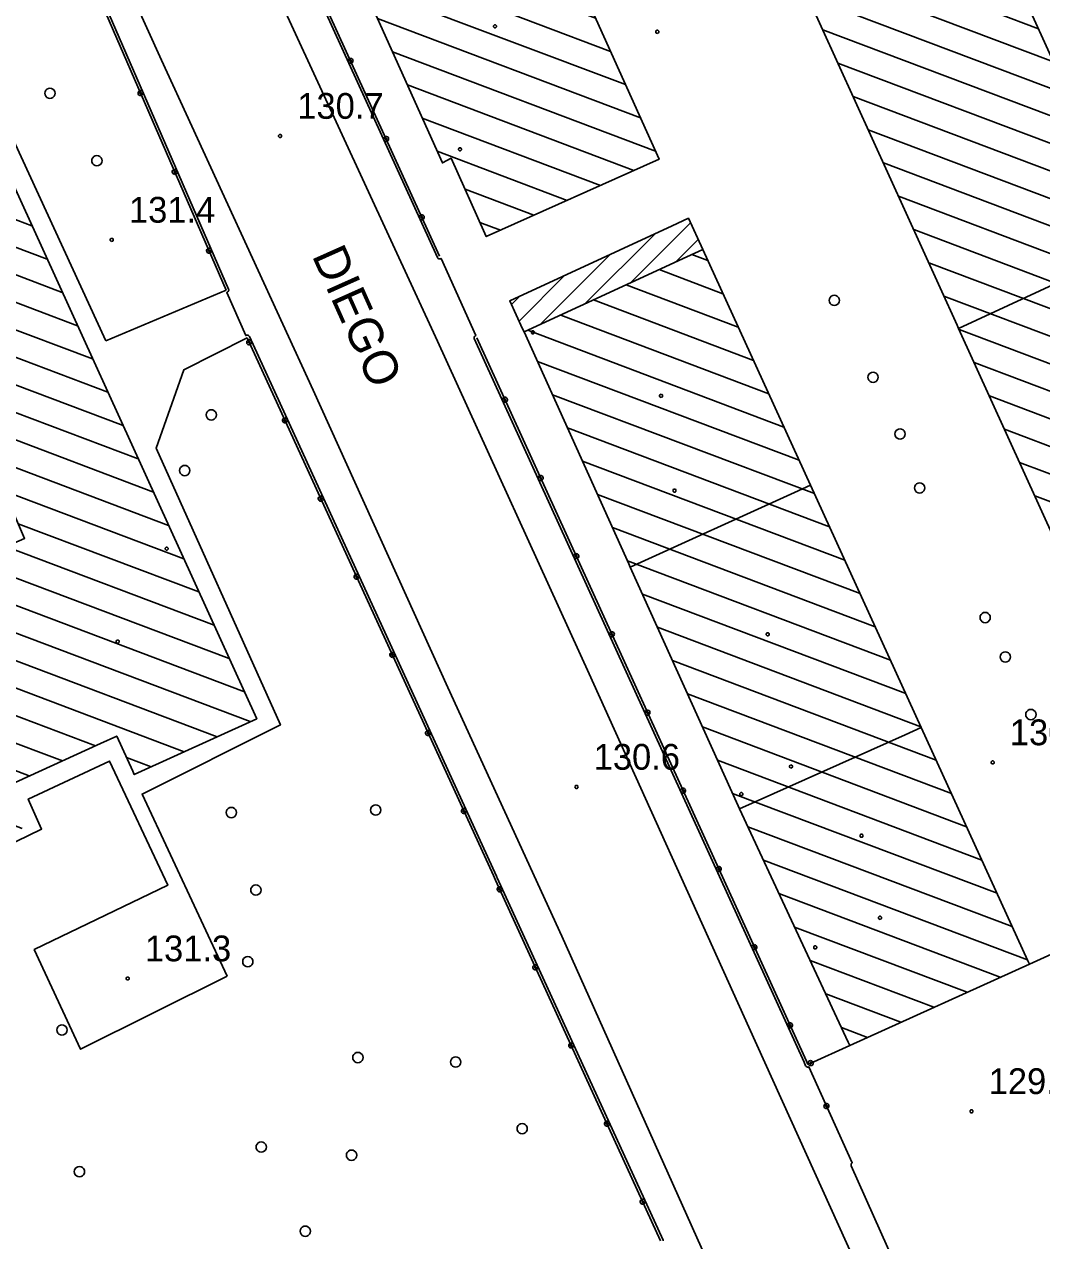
# Model space of a CAD drawing. Extents: x 513373 to 514978, y 5038576 to 5040180.
# Drawn here: x 513491.5 to 513550.7, y 5038719.9 to 5038790.7 of the extents above; entities that cross this region are included whole.
import ezdxf

# ---------------------------------------------------------------- set-up
doc = ezdxf.new("R2010")
doc.units = 0
for name, color, linetype in [('2010300', 7, 'Continuous'), ('3010204', 7, 'Continuous'), ('B1211', 7, 'Continuous'), ('C1131', 7, 'Continuous'), ('C12211', 7, 'Continuous'), ('C21111', 7, 'Continuous'), ('C2911', 7, 'Continuous'), ('C2912', 7, 'Continuous'), ('CAMP_C12211', 7, 'Continuous'), ('CAMP_C21111', 7, 'Continuous'), ('Default', 7, 'Continuous'), ('F12107', 7, 'Continuous'), ('F12131', 7, 'Continuous'), ('F12132', 7, 'Continuous'), ('G4315', 7, 'Continuous'), ('TOP500', 7, 'Continuous'), ('TOP920', 7, 'Continuous')]:
    doc.layers.add(name, color=color, linetype=linetype)

# ---------------------------------------------------------------- blocks, each defined once
blk = doc.blocks.new('CAMP_7F96C5B8')
at = {"layer": 'CAMP_C12211'}
for p, q in [((-4.396, 23.309), (-5.045, 23.554)), ((-3.525, 21.376), (-6.942, 22.667)), ((-2.655, 19.444), (-8.838, 21.78)), ((-1.784, 17.511), (-10.734, 20.893)), ((-0.913, 15.578), (-12.63, 20.006)), ((-0.042, 13.646), (-14.476, 19.1)), ((0.829, 11.713), (-13.611, 17.169)), ((1.7, 9.78), (-12.746, 15.239)), ((2.571, 7.848), (-12.64, 13.595)), ((3.442, 5.915), (-11.774, 11.665)), ((4.313, 3.983), (-10.909, 9.735)), ((5.184, 2.05), (-10.044, 7.804)), ((6.055, 0.117), (-9.179, 5.874)), ((6.926, -1.815), (-8.314, 3.943)), ((7.796, -3.748), (-6.691, 1.726)), ((8.667, -5.68), (-5.826, -0.204)), ((9.538, -7.613), (-4.96, -2.134)), ((10.409, -9.546), (-4.095, -4.065)), ((11.28, -11.478), (-3.23, -5.995)), ((12.151, -13.411), (-2.365, -7.926)), ((13.022, -15.343), (-2.259, -9.569)), ((13.893, -17.276), (-1.393, -11.5)), ((14.764, -19.209), (-0.528, -13.43)), ((13.513, -20.34), (0.337, -15.361)), ((11.572, -21.209), (1.202, -17.291)), ((9.63, -22.079), (2.067, -19.222)), ((7.689, -22.949), (3.689, -21.438)), ((5.747, -23.819), (4.554, -23.368))]:
    blk.add_line(p, q, dxfattribs=at)
blk = doc.blocks.new('CAMP_28E5D3F1')
at = {"layer": 'CAMP_C12211'}
for p, q in [((1.849, 21.59), (-0.251, 22.384)), ((2.732, 19.653), (-2.224, 21.526)), ((3.615, 17.716), (-4.197, 20.668)), ((4.498, 15.779), (-6.101, 19.784)), ((5.38, 13.842), (-5.217, 17.846)), ((-4.284, 15.89), (-6.585, 16.76)), ((-11.933, 15.574), (-13.73, 16.252)), ((-3.338, 13.929), (-8.508, 15.883)), ((6.263, 11.905), (-4.284, 15.89)), ((-1.447, 10.007), (-15.653, 15.376)), ((-2.392, 11.968), (-10.432, 15.006)), ((-0.501, 8.047), (-17.577, 14.499)), ((0.444, 6.086), (-19.5, 13.622)), ((7.146, 9.968), (-3.338, 13.929)), ((-1.298, 5.141), (-18.778, 11.746)), ((8.029, 8.03), (-2.392, 11.968)), ((8.912, 6.093), (-1.447, 10.007)), ((-3.263, 4.28), (-17.895, 9.809)), ((-3.32, 2.698), (-17.012, 7.872)), ((9.794, 4.156), (-0.501, 8.047)), ((-2.478, 0.776), (-16.129, 5.934)), ((10.677, 2.219), (0.444, 6.086)), ((3.869, -3.226), (-15.247, 3.997)), ((11.56, 0.282), (1.294, 4.161)), ((2.133, 2.241), (1.544, 2.463)), ((12.443, -1.655), (2.133, 2.241)), ((1.904, -4.087), (-14.364, 2.06)), ((2.962, 0.324), (-0.421, 1.602)), ((3.791, -1.593), (-2.387, 0.742)), ((0.01, -4.975), (-13.481, 0.123)), ((13.326, -3.592), (2.962, 0.324)), ((0.852, -6.896), (-12.598, -1.814)), ((14.208, -5.529), (3.791, -1.593)), ((15.091, -7.466), (4.624, -3.511)), ((18.623, -15.215), (-11.716, -3.751)), ((15.974, -9.403), (5.466, -5.433)), ((18.961, -16.946), (-10.833, -5.688)), ((16.857, -11.341), (4.746, -6.764)), ((17.038, -17.823), (-9.95, -7.625)), ((17.74, -13.278), (2.78, -7.625)), ((15.114, -18.7), (-9.067, -9.562)), ((9.957, -18.354), (-8.184, -11.499)), ((8.034, -19.231), (-7.302, -13.436)), ((6.11, -20.108), (-6.419, -15.374)), ((4.812, -21.221), (-5.536, -17.311)), ((13.19, -19.576), (11.759, -19.035)), ((5.695, -23.158), (-4.653, -19.248)), ((3.82, -24.053), (-3.77, -21.185)), ((1.896, -24.93), (-2.888, -23.122)), ((-0.027, -25.806), (-2.005, -25.059))]:
    blk.add_line(p, q, dxfattribs=at)
blk = doc.blocks.new('CAMP_A73D41F0')
at = {"layer": 'CAMP_C12211'}
for p, q in [((-3.931, 22.331), (-4.849, 22.678)), ((-3.045, 20.393), (-6.758, 21.796)), ((-2.159, 18.455), (-8.668, 20.914)), ((-1.274, 16.516), (-10.577, 20.032)), ((-0.388, 14.578), (-12.486, 19.15)), ((0.498, 12.64), (-14.395, 18.268)), ((1.383, 10.702), (-13.834, 16.452)), ((2.269, 8.764), (-12.962, 14.519)), ((3.155, 6.826), (-12.09, 12.586)), ((4.04, 4.887), (-11.218, 10.653)), ((4.926, 2.949), (-10.346, 8.72)), ((5.811, 1.011), (-9.474, 6.787)), ((6.697, -0.927), (-8.603, 4.854)), ((7.582, -2.865), (-7.73, 2.921)), ((8.468, -4.803), (-6.858, 0.988)), ((9.354, -6.741), (-5.986, -0.945)), ((10.239, -8.68), (-5.114, -2.878)), ((11.125, -10.618), (-4.241, -4.811)), ((12.011, -12.556), (-3.369, -6.744)), ((12.896, -14.494), (-2.497, -8.678)), ((13.782, -16.432), (-1.606, -10.618)), ((14.667, -18.37), (-0.698, -12.565)), ((13.082, -19.375), (0.21, -14.511)), ((11.153, -20.25), (1.119, -16.458)), ((9.224, -21.124), (2.027, -18.405)), ((7.295, -21.999), (2.935, -20.351)), ((5.366, -22.874), (3.843, -22.298))]:
    blk.add_line(p, q, dxfattribs=at)
blk = doc.blocks.new('CAMP_EDF7B2BA')
at = {"layer": 'CAMP_C12211'}
for p, q in [((5.233, 2.031), (-9.956, 7.771)), ((6.113, 0.095), (-9.075, 5.834)), ((6.994, -1.841), (-8.194, 3.898)), ((7.874, -3.777), (-7.314, 1.962)), ((8.754, -5.713), (-6.433, 0.026)), ((9.635, -7.649), (-5.552, -1.911)), ((10.515, -9.586), (-4.672, -3.847)), ((11.394, -11.521), (-3.791, -5.783)), ((12.272, -13.457), (-2.91, -7.72)), ((13.15, -15.392), (-2.029, -9.656)), ((14.028, -17.327), (-1.149, -11.592)), ((14.906, -19.263), (-0.268, -13.529)), ((15.785, -21.198), (0.613, -15.465)), ((16.663, -23.133), (1.493, -17.401)), ((17.541, -25.069), (2.374, -19.338)), ((18.419, -27.004), (3.255, -21.274)), ((19.297, -28.939), (4.135, -23.21)), ((20.175, -30.874), (5.016, -25.146))]:
    blk.add_line(p, q, dxfattribs=at)
blk = doc.blocks.new('CAMP_EE068C11')
at = {"layer": 'CAMP_C21111'}
for p, q in [((1.755, -0.366), (5.261, 3.139)), ((-0.874, -1.581), (3.222, 2.515)), ((4.384, 0.848), (5.708, 2.172)), ((-3.502, -2.795), (0.594, 1.301)), ((-4.701, -2.58), (-2.035, 0.086)), ((-5.148, -1.613), (-4.664, -1.128))]:
    blk.add_line(p, q, dxfattribs=at)
blk = doc.blocks.new('03080200')
at = {"layer": 'Default'}
for p, q in [((-0.139, 0.046), (-0.146, 0)), ((-0.146, 0), (-0.139, -0.046)), ((-0.118, 0.086), (-0.139, 0.046)), ((-0.086, 0.118), (-0.118, 0.086)), ((-0.046, 0.139), (-0.086, 0.118)), ((0, 0.146), (-0.046, 0.139)), ((-0.042, 0.014), (-0.045, 0)), ((-0.045, 0), (-0.042, -0.014)), ((-0.036, 0.026), (-0.042, 0.014)), ((-0.026, 0.036), (-0.036, 0.026)), ((-0.014, 0.042), (-0.026, 0.036)), ((0, 0.045), (-0.014, 0.042)), ((0.046, 0.139), (0, 0.146)), ((0.014, 0.042), (0, 0.045)), ((0.026, 0.036), (0.014, 0.042)), ((0.036, 0.026), (0.026, 0.036)), ((0.042, 0.014), (0.036, 0.026)), ((0.045, 0), (0.042, 0.014)), ((0.042, -0.014), (0.045, 0)), ((0.086, 0.118), (0.046, 0.139)), ((0.118, 0.086), (0.086, 0.118)), ((0.139, 0.046), (0.118, 0.086)), ((0.146, 0), (0.139, 0.046)), ((0.139, -0.046), (0.146, 0)), ((-0.139, -0.046), (-0.118, -0.086)), ((-0.118, -0.086), (-0.086, -0.118)), ((-0.086, -0.118), (-0.046, -0.139)), ((-0.046, -0.139), (0, -0.146)), ((-0.042, -0.014), (-0.036, -0.026)), ((-0.036, -0.026), (-0.026, -0.036)), ((-0.026, -0.036), (-0.014, -0.042)), ((-0.014, -0.042), (0, -0.045)), ((0, -0.045), (0.014, -0.042)), ((0, -0.146), (0.046, -0.139)), ((0.014, -0.042), (0.026, -0.036)), ((0.026, -0.036), (0.036, -0.026)), ((0.036, -0.026), (0.042, -0.014)), ((0.046, -0.139), (0.086, -0.118)), ((0.086, -0.118), (0.118, -0.086)), ((0.118, -0.086), (0.139, -0.046))]:
    blk.add_line(p, q, dxfattribs=at)
blk = doc.blocks.new('08020400')
at = {"layer": 'Default'}
for p, q in [((-0.086, 0.028), (-0.09, 0)), ((-0.09, 0), (-0.086, -0.028)), ((-0.073, 0.053), (-0.086, 0.028)), ((-0.053, 0.073), (-0.073, 0.053)), ((-0.028, 0.086), (-0.053, 0.073)), ((0, 0.09), (-0.028, 0.086)), ((0.028, 0.086), (0, 0.09)), ((0.053, 0.073), (0.028, 0.086)), ((0.073, 0.053), (0.053, 0.073)), ((0.086, 0.028), (0.073, 0.053)), ((0.09, 0), (0.086, 0.028)), ((0.086, -0.028), (0.09, 0)), ((-0.086, -0.028), (-0.073, -0.053)), ((-0.073, -0.053), (-0.053, -0.073)), ((-0.053, -0.073), (-0.028, -0.086)), ((-0.028, -0.086), (0, -0.09)), ((0, -0.09), (0.028, -0.086)), ((0.028, -0.086), (0.053, -0.073)), ((0.053, -0.073), (0.073, -0.053)), ((0.073, -0.053), (0.086, -0.028))]:
    blk.add_line(p, q, dxfattribs=at)
blk = doc.blocks.new('NSIMB25')
at = {"layer": 'Default'}
for p, q in [((-0.086, 0.028), (-0.09, 0)), ((-0.09, 0), (-0.086, -0.028)), ((-0.073, 0.053), (-0.086, 0.028)), ((-0.053, 0.073), (-0.073, 0.053)), ((-0.028, 0.086), (-0.053, 0.073)), ((0, 0.09), (-0.028, 0.086)), ((0.028, 0.086), (0, 0.09)), ((0.053, 0.073), (0.028, 0.086)), ((0.073, 0.053), (0.053, 0.073)), ((0.086, 0.028), (0.073, 0.053)), ((0.09, 0), (0.086, 0.028)), ((0.086, -0.028), (0.09, 0)), ((-0.086, -0.028), (-0.073, -0.053)), ((-0.073, -0.053), (-0.053, -0.073)), ((-0.053, -0.073), (-0.028, -0.086)), ((-0.028, -0.086), (0, -0.09)), ((0, -0.09), (0.028, -0.086)), ((0.028, -0.086), (0.053, -0.073)), ((0.053, -0.073), (0.073, -0.053)), ((0.073, -0.053), (0.086, -0.028))]:
    blk.add_line(p, q, dxfattribs=at)
blk = doc.blocks.new('05010100')
at = {"layer": 'Default'}
for p, q in [((-0.143, 0.046), (-0.15, 0)), ((-0.15, 0), (-0.143, -0.046)), ((-0.121, 0.088), (-0.143, 0.046)), ((-0.088, 0.121), (-0.121, 0.088)), ((-0.046, 0.143), (-0.088, 0.121)), ((0, 0.15), (-0.046, 0.143)), ((0.046, 0.143), (0, 0.15)), ((0.088, 0.121), (0.046, 0.143)), ((0.121, 0.088), (0.088, 0.121)), ((0.143, 0.046), (0.121, 0.088)), ((0.15, 0), (0.143, 0.046)), ((0.143, -0.046), (0.15, 0)), ((-0.143, -0.046), (-0.121, -0.088)), ((-0.121, -0.088), (-0.088, -0.121)), ((-0.088, -0.121), (-0.046, -0.143)), ((-0.046, -0.143), (0, -0.15)), ((0, -0.15), (0.046, -0.143)), ((0.046, -0.143), (0.088, -0.121)), ((0.088, -0.121), (0.121, -0.088)), ((0.121, -0.088), (0.143, -0.046))]:
    blk.add_line(p, q, dxfattribs=at)
blk = doc.blocks.new('A$C3704598A')
at = {"layer": '2010300'}
for points in [[(142.738, -603.093), (144.768, -607.577)], [(131.377, -607.587), (130.272, -605.078)]]:
    blk.add_lwpolyline(points, dxfattribs=at)
at = {"layer": '3010204'}
for points in [[(123.244, -607.886), (113.934, -587.68), (116.864, -587.123), (119.4, -586.47), (121.933, -585.805)], [(130.239, -604.934), (123.244, -607.886)], [(130.306, -644.861), (125.353, -634.257), (133.396, -630.235), (126.165, -614.132), (127.781, -609.571), (131.459, -607.71)], [(104.013, -625.817), (110.125, -639.589), (106.745, -641.211), (109.435, -647.409), (102.653, -650.535), (105.434, -656.85), (113.453, -653.038), (108.366, -641.711), (119.508, -636.299), (118.733, -634.551), (123.464, -632.337), (126.843, -639.562), (119.08, -643.308), (121.773, -649.111), (130.306, -644.861)]]:
    blk.add_lwpolyline(points, dxfattribs=at)
at = {"layer": 'B1211'}
for points in [[(122.509, -559.099), (142.528, -603.047), (142.549, -603.076), (142.572, -603.094), (142.603, -603.11), (142.636, -603.119), (142.67, -603.119), (142.699, -603.113), (142.738, -603.093), (144.768, -607.577), (144.721, -607.603), (144.693, -607.634), (144.675, -607.672), (144.668, -607.712), (144.673, -607.754), (163.852, -649.867), (163.943, -650.066), (163.976, -650.107), (164.018, -650.132), (164.054, -650.142), (164.088, -650.142), (164.126, -650.132), (166.659, -655.717), (166.628, -655.741), (166.609, -655.763), (166.596, -655.789), (166.586, -655.824), (166.585, -655.865), (166.592, -655.895), (173.493, -671.359)], [(178.888, -672.206), (176.406, -672.89), (176.1, -672.93), (175.755, -672.975), (174.978, -672.987), (174.361, -672.84), (173.877, -672.725), (172.726, -672.083), (172.349, -671.829), (171.665, -671.369), (170.95, -670.389), (170.541, -669.571), (168.285, -664.691), (160.651, -647.821), (151.346, -627.269), (142.537, -607.914), (132.751, -586.689), (123.465, -566.119), (117.038, -551.754), (103.489, -521.985), (94.591, -502.503), (88.175, -488.246)], [(84.441, -498.839), (91.117, -513.605), (97.67, -527.991), (106.443, -547.22), (113.013, -561.806), (120.311, -577.932), (126.473, -591.555), (135.3, -610.767), (143.131, -628.055), (149.774, -642.531), (159.201, -663.609)], [(155.662, -660.25), (155.653, -660.208), (146, -639.138), (145.987, -639.089), (145.961, -639.039), (131.589, -607.637), (131.565, -607.604), (131.539, -607.583), (131.503, -607.567), (131.464, -607.56), (131.426, -607.565), (131.377, -607.587), (130.272, -605.078), (130.318, -605.06), (130.345, -605.039), (130.366, -605.012), (130.379, -604.986), (130.387, -604.958), (130.388, -604.919), (130.38, -604.884), (122.787, -587.398)]]:
    blk.add_lwpolyline(points, dxfattribs=at)
at = {"layer": 'C1131'}
for points in [[(183.231, -602.351), (182.295, -602.784), (172.843, -607.161), (172.755, -606.967), (153.975, -565.678), (147.624, -551.714), (152.947, -549.285), (152.179, -547.483), (156.299, -545.61), (157.239, -545.182)], [(135.845, -553.872), (155.423, -597.317), (145.367, -601.823), (145.286, -601.641), (143.323, -597.26), (142.819, -597.539), (137.905, -586.573), (138.417, -586.309), (132.906, -574.013), (132.394, -574.275), (127.48, -563.311), (127.999, -563.062), (125.954, -558.499), (134.909, -554.31)], [(157.962, -602.574), (157.026, -603.007), (147.575, -607.373), (147.486, -607.181), (146.736, -605.557), (156.188, -601.19), (157.123, -600.758)], [(164.229, -616.288), (163.291, -616.715), (153.747, -621.055), (153.662, -620.867), (147.575, -607.373), (157.026, -603.007), (157.962, -602.574)], [(192.763, -623.359), (191.822, -623.779), (182.329, -628.018), (182.246, -627.836), (172.843, -607.161), (182.295, -602.784), (183.231, -602.351)], [(170.674, -630.393), (169.733, -630.815), (160.097, -635.128), (160.015, -634.946), (153.747, -621.055), (163.291, -616.715), (164.229, -616.288)], [(176.96, -644.15), (166.515, -648.885), (166.428, -648.699), (160.097, -635.128), (169.733, -630.815), (170.674, -630.393), (176.874, -643.962)]]:
    blk.add_lwpolyline(points, close=True, dxfattribs=at)
for points in [[(114.112, -621.316), (118.521, -619.385), (117.079, -616.094)], [(113.882, -590.085), (132.016, -629.876), (124.891, -633.123), (124.806, -632.935), (123.874, -630.891), (122.936, -631.318), (117.297, -633.889)]]:
    blk.add_lwpolyline(points, dxfattribs=at)
at = {"layer": 'C12211'}
for points in [[(197.915, -634.647), (187.494, -639.373), (187.408, -639.185), (182.329, -628.018), (182.246, -627.836), (172.843, -607.161), (172.755, -606.967), (153.975, -565.678), (147.624, -551.714), (152.947, -549.285), (152.179, -547.483), (156.299, -545.61), (157.239, -545.182), (183.231, -602.351), (192.763, -623.359), (194.725, -627.649), (195.345, -629.01), (197.829, -634.459)], [(135.845, -553.872), (155.423, -597.317), (145.367, -601.823), (145.286, -601.641), (143.323, -597.26), (142.819, -597.539), (137.905, -586.573), (138.417, -586.309), (132.906, -574.013), (132.394, -574.275), (127.48, -563.311), (127.999, -563.062), (125.954, -558.499), (134.909, -554.31)], [(176.96, -644.15), (166.515, -648.885), (166.428, -648.699), (160.097, -635.128), (160.015, -634.946), (153.747, -621.055), (153.662, -620.867), (147.575, -607.373), (157.026, -603.007), (157.962, -602.574), (164.229, -616.288), (170.674, -630.393), (176.874, -643.962)]]:
    blk.add_lwpolyline(points, close=True, dxfattribs=at)
for points in [[(114.112, -621.316), (118.521, -619.385), (117.079, -616.094)], [(113.882, -590.085), (132.016, -629.876), (124.891, -633.123), (124.806, -632.935), (123.874, -630.891), (122.936, -631.318), (117.297, -633.889)]]:
    blk.add_lwpolyline(points, dxfattribs=at)
at = {"layer": 'C21111'}
blk.add_lwpolyline([(157.962, -602.574), (157.026, -603.007), (147.575, -607.373), (147.486, -607.181), (146.736, -605.557), (156.188, -601.19), (157.123, -600.758)], close=True, dxfattribs=at)
at = {"layer": 'C2911'}
for points in [[(142.655, -602.97), (122.648, -559.044)], [(130.239, -604.934), (118.932, -578.895), (118.814, -578.622)], [(155.513, -660.257), (145.906, -639.271), (145.782, -639), (131.459, -607.71)], [(164.073, -649.993), (163.987, -649.806), (144.817, -607.717)]]:
    blk.add_lwpolyline(points, dxfattribs=at)
at = {"layer": 'C2912'}
for points in [[(187.494, -639.373), (176.96, -644.15)], [(166.515, -648.885), (164.21, -649.93)], [(164.126, -650.132), (166.659, -655.717)]]:
    blk.add_lwpolyline(points, dxfattribs=at)
at = {"layer": 'C2911'}
for p, rotation in [((137.474, -591.594), 114.48809176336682), ((125.261, -593.468), 113.47283509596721), ((139.547, -596.145), 114.48809176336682), ((127.252, -598.054), 113.47283509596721), ((141.619, -600.695), 114.48809176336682), ((129.244, -602.641), 113.47283509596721), ((131.58, -607.974), 114.59563128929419), ((146.457, -611.316), 114.48760196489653), ((133.662, -612.521), 114.59563128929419), ((148.529, -615.866), 114.48760196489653), ((135.743, -617.067), 114.59563128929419), ((150.602, -620.417), 114.48760196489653), ((137.824, -621.613), 114.59563128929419), ((152.674, -624.967), 114.48760196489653), ((139.905, -626.16), 114.59563128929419), ((154.747, -629.517), 114.48760196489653), ((141.986, -630.706), 114.59563128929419), ((156.819, -634.067), 114.48760196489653), ((144.067, -635.252), 114.59563128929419), ((158.891, -638.618), 114.48760196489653), ((146.148, -639.799), 114.5956312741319), ((160.964, -643.168), 114.48760196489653), ((148.229, -644.345), 114.5956312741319), ((163.036, -647.718), 114.48760196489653), ((150.31, -648.891), 114.5956312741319), ((152.391, -653.438), 114.5956312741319), ((154.472, -657.984), 114.5956312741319)]:
    blk.add_blockref('03080200', p, dxfattribs=dict(at, rotation=rotation))
at = {"layer": 'C2912'}
for p, rotation in [((164.238, -649.918), -155.61302354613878), ((165.158, -652.409), -65.60484175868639)]:
    blk.add_blockref('03080200', p, dxfattribs=dict(at, rotation=rotation))
at = {"layer": 'CAMP_C12211'}
for name, p in [('CAMP_EDF7B2BA', (172.258, -591.756)), ('CAMP_7F96C5B8', (140.446, -577.634)), ('CAMP_28E5D3F1', (112.682, -613.099)), ('CAMP_A73D41F0', (162.184, -625.542))]:
    blk.add_blockref(name, p, dxfattribs=at)
at = {"layer": 'CAMP_C21111'}
blk.add_blockref('CAMP_EE068C11', (151.984, -604.159), dxfattribs=at)
at = {"layer": 'F12107'}
for p in [(155.315, -589.906), (133.379, -595.969), (123.588, -602.012), (174.822, -632.419), (150.618, -633.843), (124.513, -644.992), (173.593, -652.718)]:
    blk.add_blockref('08020400', p, dxfattribs=at)
at = {"layer": 'F12131'}
for p in [(156.317, -616.601), (123.931, -625.384), (163.093, -632.657), (168.274, -641.46)]:
    blk.add_blockref('NSIMB25', p, dxfattribs=at)
at = {"layer": 'F12132'}
for p in [(145.881, -589.585), (143.838, -596.74), (148.082, -607.396), (155.539, -611.087), (126.778, -619.981), (161.742, -624.961), (160.201, -634.263), (167.195, -636.687), (164.504, -643.183)]:
    blk.add_blockref('NSIMB25', p, dxfattribs=at)
at = {"layer": 'G4315', "xscale": 2, "yscale": 2}
for p in [(119.992, -593.484), (122.723, -597.407), (165.612, -605.536), (167.866, -610.008), (129.374, -612.196), (169.438, -613.308), (127.831, -615.434), (170.574, -616.448), (174.388, -623.988), (175.561, -626.283), (177.045, -629.632), (130.542, -635.337), (138.94, -635.188), (131.968, -639.845), (131.501, -644.013), (120.689, -647.988), (137.903, -649.59), (143.589, -649.852), (147.458, -653.73), (132.281, -654.799), (137.532, -655.275), (121.706, -656.231), (134.842, -659.696)]:
    blk.add_blockref('05010100', p, dxfattribs=at)
at = {"layer": 'TOP500'}
blk.add_text('DIEGO', height=2, rotation=294.10207, dxfattribs=at).set_placement((135.206, -602.921))
at = {"layer": 'TOP920'}
for s, p in [('130.7', (134.379, -594.969)), ('131.4', (124.588, -601.012)), ('130.7', (175.822, -631.419)), ('130.6', (151.618, -632.843)), ('131.3', (125.513, -643.992)), ('129.1', (174.593, -651.718))]:
    blk.add_text(s, height=1.5, dxfattribs=at).set_placement(p)

msp = doc.modelspace()

# ---------------------------------------------------------------- block references
at = {"layer": 'Default'}
msp.add_blockref('A$C3704598A', (513373.046, 5039380.14), dxfattribs=at)

doc.saveas('drawing.dxf')
